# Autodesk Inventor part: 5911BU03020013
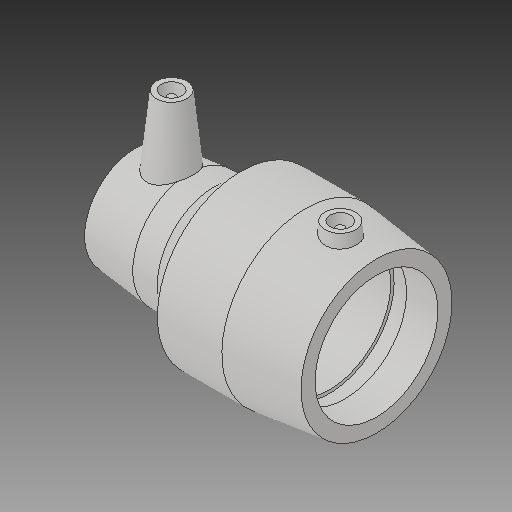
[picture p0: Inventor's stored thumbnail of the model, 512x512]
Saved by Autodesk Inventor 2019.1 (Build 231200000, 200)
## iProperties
Created: 2017-06
Part Number: 5911BU03020013
Material: Generic
Description: PLASSON ASTM REDUCING COUPLER 2''IPS-1 1/4''CTS
Document SubType Name: Modeling
Designer: KIM
Mass: 54.8237 g
Surface Area: 155.252 cm^2
Volume: 54.8237 cm^3
Density: 1 g/cm^3
Appearance: Default
Author: KIM
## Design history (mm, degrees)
derived "5911.ipt"
feature "Solid1::5911.ipt"
tag "TaggingFeature1"
body "Solid1"
other parameters: "d0" = 117.856, "d2" = 55.372, "d3" = 43.942, "d4" = 26.3652, "d5" = 49.8348, "d7" = 34.8, "d8" = 168 deg, "d10" = 17.5768, "d11" = 5.85893, "d14" = 17.6296, "d22" = 108.92847, "d29" = 58.42, "d30" = 15, "d31" = 41.2496, "d34" = 6 deg, "d41" = 4, "d42" = 14, "d43" = 0, "d48" = 55.372, "d49" = 60.1, "d50" = 82.042, "d52" = 31.32, "d53" = 23.0632, "d54" = 7.68773, "d55" = 168 deg, "d56" = 34.5948, "d57" = 57.658, "d58" = 73.8378, "d59" = 2.1971, "d60" = 135 deg, "d61" = 44.196, "d62" = 15, "d64" = 4, "d66" = 5 deg, "d67" = 14, "d68" = 0, "d69" = 41.2496, "d95" = 3, "d96" = 0, "d97" = 3, "d98" = 0, "d_1" = 34.8, "L_" = 117.856, "L_2" = 43.942, "D_1" = 55.372, "A_1" = 58.42, "d_2" = 12, "L_1" = 57.658, "d_" = 60.1, "A_" = 44.196, "D_" = 82.042
